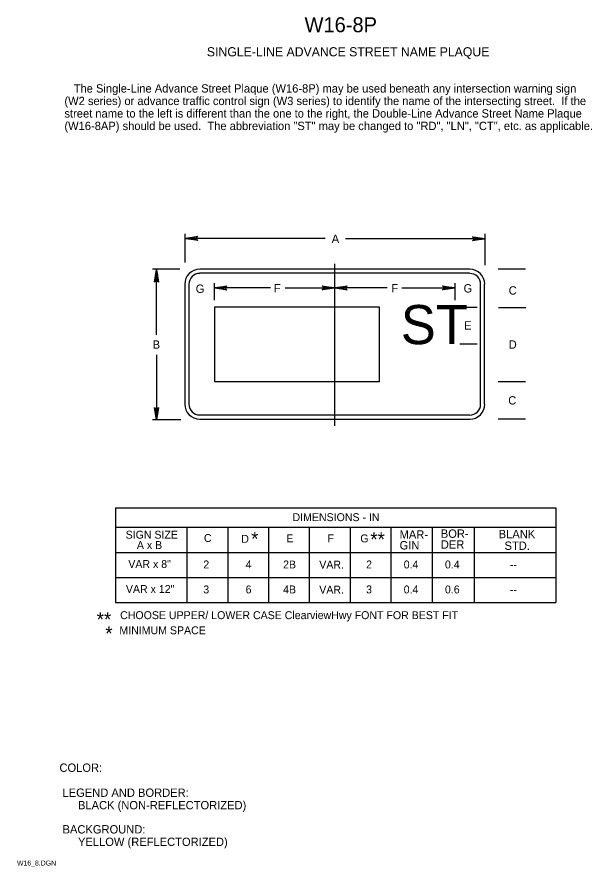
# Model space of a CAD drawing. Extents: x 0.013 to 0.185, y 0.004 to 0.259.
import ezdxf

# ---------------------------------------------------------------- set-up
doc = ezdxf.new("R2010")
doc.units = 0
for name, color, linetype in [('1', 7, 'Continuous'), ('2', 7, 'Continuous'), ('3', 7, 'Continuous')]:
    doc.layers.add(name, color=color, linetype=linetype)

# ---------------------------------------------------------------- blocks, each defined once
blk = doc.blocks.new('RARROW')
at = {"layer": '3'}
for p, q in [((-2.156, 0.285), (-2.2665, 0.384625)), ((-2.2665, 0.384625), (0, 0)), ((0, 0), (-2.2665, -0.379125)), ((-2.156, 0.285), (-2.075625, 0.12075)), ((0, 0), (-2.156, 0.285)), ((-2.14975, -0.2705), (0, 0)), ((-2.075625, 0.12075), (0, 0)), ((0, 0), (-2.074, -0.108)), ((-2.2665, -0.379125), (-2.14975, -0.2705)), ((-2.074, -0.108), (-2.14975, -0.2705))]:
    blk.add_line(p, q, dxfattribs=at)

msp = doc.modelspace()

# ---------------------------------------------------------------- linework, layer by layer
at = {"layer": '1'}
msp.add_line((0.108, 0.185), (0.108, 0.13637), dxfattribs=at)
msp.add_lwpolyline([(0.07203, 0.17204), (0.1214, 0.17204), (0.1214, 0.14959), (0.07203, 0.14959)], close=True, dxfattribs=at)
at = {"layer": '3'}
for p, q in [((0.06313, 0.18534), (0.06313, 0.19396)), ((0.15317, 0.18459), (0.15317, 0.19396)), ((0.10518, 0.19262), (0.06313, 0.19262)), ((0.11123, 0.19257), (0.15312, 0.19257)), ((0.0615, 0.18334), (0.05329, 0.18334)), ((0.0545, 0.16372), (0.0545, 0.18334)), ((0.1485, 0.18338), (0.0675, 0.18338)), ((0.1485, 0.18213), (0.0675, 0.18213)), ((0.1653, 0.18334), (0.15709, 0.18334)), ((0.063, 0.17888), (0.063, 0.14287)), ((0.06425, 0.17888), (0.06425, 0.14287)), ((0.07189, 0.17409), (0.07189, 0.17913)), ((0.108, 0.18088), (0.108, 0.17913)), ((0.14417, 0.17409), (0.14417, 0.17913)), ((0.15175, 0.14287), (0.15175, 0.17888)), ((0.153, 0.14287), (0.153, 0.17888)), ((0.08878, 0.17775), (0.07188, 0.17775)), ((0.09312, 0.17775), (0.108, 0.17775)), ((0.12375, 0.17775), (0.108, 0.17775)), ((0.12812, 0.17775), (0.14417, 0.17775)), ((0.15075, 0.17191), (0.14556, 0.17191)), ((0.16542, 0.17173), (0.15721, 0.17173)), ((0.15075, 0.16084), (0.14556, 0.16084)), ((0.0545, 0.15767), (0.0545, 0.13821)), ((0.1653, 0.14959), (0.15709, 0.14959)), ((0.06185, 0.13816), (0.05327, 0.13816)), ((0.0675, 0.13962), (0.1485, 0.13962)), ((0.0675, 0.13837), (0.1485, 0.13837)), ((0.1653, 0.13834), (0.15709, 0.13834)), ((0.04225, 0.11175), (0.17438, 0.11175)), ((0.04225, 0.11175), (0.04225, 0.08338)), ((0.17438, 0.11175), (0.17438, 0.08338)), ((0.17438, 0.10587), (0.04225, 0.10587)), ((0.06364, 0.1058), (0.06364, 0.08338)), ((0.07589, 0.1058), (0.07589, 0.08338)), ((0.08814, 0.1058), (0.08814, 0.08338)), ((0.10039, 0.1058), (0.10039, 0.08338)), ((0.11264, 0.1058), (0.11264, 0.08338)), ((0.12489, 0.1058), (0.12489, 0.08338)), ((0.13729, 0.1058), (0.13729, 0.08338)), ((0.14984, 0.1058), (0.14984, 0.08338)), ((0.04225, 0.09838), (0.17438, 0.09838)), ((0.04225, 0.09087), (0.17438, 0.09087)), ((0.04225, 0.08338), (0.17438, 0.08338))]:
    msp.add_line(p, q, dxfattribs=at)
for centre, radius, start, end in [((0.06752, 0.17886), 0.00452, 90.2314, 180.2314), ((0.06752, 0.17885), 0.00327, 90.3879, 180.3879), ((0.14856, 0.17884), 0.0045, 0, 90), ((0.14856, 0.17884), 0.00325, 0, 90), ((0.0675, 0.14287), 0.0045, 180, 270), ((0.0675, 0.14287), 0.00325, 180, 270), ((0.14856, 0.14284), 0.0045, 270, 0), ((0.14856, 0.14284), 0.00325, 270, 0)]:
    msp.add_arc(centre, radius, start, end, dxfattribs=at)

# ---------------------------------------------------------------- block references
at = {"layer": '3', "xscale": 0.0016545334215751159, "yscale": 0.0016366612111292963}
for p, rotation in [((0.06313, 0.19262), 180), ((0.0545, 0.18325), 90), ((0.07188, 0.17775), 180), ((0.108, 0.17775), 180), ((0.0545, 0.13812), -90)]:
    msp.add_blockref('RARROW', p, dxfattribs=dict(at, rotation=rotation))
for p in [(0.15313, 0.1925), (0.108, 0.17775), (0.14413, 0.17775)]:
    msp.add_blockref('RARROW', p, dxfattribs=at)

# ---------------------------------------------------------------- texts
at = {"layer": '1'}
for s, height, p in [('W16-8P', 0.0045, (0.09897, 0.2545)), ('SINGLE-LINE ADVANCE STREET NAME PLAQUE', 0.0027503, (0.06964, 0.24725)), ('G', 0.0025, (0.06629, 0.17626)), ('G', 0.0025, (0.14671, 0.17638)), ('*', 0.0042, (0.08293, 0.10034)), ('**', 0.0042, (0.1187, 0.1002)), ('--', 0.002375, (0.16062, 0.0935)), ('--', 0.002375, (0.16062, 0.086)), ('**', 0.0042, (0.03656, 0.07616)), ('CHOOSE UPPER/ LOWER CASE ClearviewHwy FONT FOR BEST FIT', 0.0023752, (0.0436, 0.07834)), ('*', 0.0042, (0.03914, 0.07193)), ('MINIMUM SPACE', 0.0023752, (0.04338, 0.0738)), ('COLOR:', 0.0025, (0.02538, 0.0325)), (' LEGEND AND BORDER:', 0.0024998, (0.02538, 0.025)), ('      BLACK (NON-REFLECTORIZED)', 0.0024998, (0.02538, 0.02125)), (' BACKGROUND:', 0.0024998, (0.02538, 0.014)), ('      YELLOW (REFLECTORIZED)', 0.0024998, (0.02538, 0.01025)), ('W16_8.DGN', 0.0015, (0.01263, 0.00438))]:
    msp.add_text(s, height=height, dxfattribs=at).set_placement(p)
at = {"layer": '2'}
for s, height, p in [('   The Single-Line Advance Street Plaque (W16-8P) may be used beneath any intersection warning sign ', 0.0024998, (0.02687, 0.23638)), ('(W2 series) or advance traffic control sign (W3 series) to identify the name of the intersecting street.  If the ', 0.00249975, (0.02687, 0.23263)), ('street name to the left is different than the one to the right, the Double-Line Advance Street Name Plaque', 0.00249975, (0.02687, 0.22888)), ('(W16-8AP) should be used.  The abbreviation "ST" may be changed to "RD", "LN", "CT", etc. as applicable.', 0.00249975, (0.02687, 0.22513))]:
    msp.add_text(s, height=height, dxfattribs=at).set_placement(p)
at = {"layer": '3'}
for s, height, p in [('A', 0.0025, (0.10712, 0.19125)), ('F', 0.0025, (0.08975, 0.17638)), ('F', 0.0025, (0.125, 0.17638)), ('C', 0.0025, (0.16025, 0.17575)), ('ST', 0.01175, (0.12788, 0.16087)), ('E', 0.0025, (0.14688, 0.16525)), ('B', 0.0025, (0.05337, 0.1595)), ('D', 0.0025, (0.16025, 0.1595)), ('C', 0.0025, (0.16012, 0.14275)), ('DIMENSIONS - IN', 0.0023752, (0.09535, 0.10775)), ('SIGN SIZE', 0.002375, (0.04525, 0.1025)), ('MAR-', 0.0025, (0.1275, 0.1025)), ('BOR-', 0.0025, (0.13987, 0.10275)), ('BLANK', 0.0025, (0.15725, 0.10263)), ('C', 0.00238, (0.06875, 0.1015)), ('D', 0.00238, (0.07997, 0.10125)), ('E', 0.00238, (0.0935, 0.10138)), ('F', 0.00238, (0.10587, 0.10138)), ('G', 0.00238, (0.1157, 0.10138)), ('A x B', 0.002375, (0.04863, 0.09938)), ('GIN', 0.0025, (0.1275, 0.09925)), ('DER', 0.0025, (0.13987, 0.0995)), ('STD.', 0.0025, (0.159, 0.09913)), ('VAR x 8"', 0.002375, (0.04605, 0.09369)), ('2', 0.00238, (0.06857, 0.09356)), ('4', 0.00238, (0.08126, 0.09356)), ('2B', 0.002375, (0.09252, 0.09356)), ('VAR.', 0.002375, (0.10338, 0.0935)), ('2', 0.00238, (0.11745, 0.09356)), ('0.4', 0.002375, (0.12873, 0.09356)), ('0.4', 0.002375, (0.14111, 0.09356)), ('VAR x 12"', 0.002375, (0.04533, 0.08619)), ('3', 0.00238, (0.06856, 0.08606)), ('6', 0.00238, (0.08127, 0.08606)), ('4B', 0.002375, (0.09252, 0.08606)), ('VAR.', 0.002375, (0.10338, 0.086)), ('3', 0.00238, (0.11743, 0.08606)), ('0.4', 0.002375, (0.12873, 0.08606)), ('0.6', 0.002375, (0.14112, 0.08606))]:
    msp.add_text(s, height=height, dxfattribs=at).set_placement(p)

doc.saveas('drawing.dxf')
